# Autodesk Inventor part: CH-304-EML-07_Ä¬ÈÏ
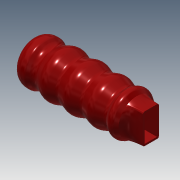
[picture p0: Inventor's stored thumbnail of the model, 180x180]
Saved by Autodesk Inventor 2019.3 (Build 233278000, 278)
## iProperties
Created: 2010-06
Part Number: CH-304-EML-07_Ä¬ÈÏ
Material: Ogólny
Document SubType Name: Modeling
Designer: CADENGINEERING4
Density: 1 g/cm^3
Appearance: Czerwona
Author: CADENGINEERING4
Revision Number: ÈÎºÎ
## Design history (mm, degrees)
feature "NONE"
node "Bryła1"
